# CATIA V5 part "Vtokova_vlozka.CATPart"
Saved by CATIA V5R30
Part number: Vtokova_vlozka
Definition: EH 6400_12_30x43_0
Nomenclature: EH 6400_12_30x43_0
Source: Unknown
Description: PART--DESC
Bounding box of the stored display mesh (mm): x -19.55 to 19.55, y -19.55 to 19.55, z 77.7 to 132.7
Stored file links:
  E:\Bakalarka\Model\Forma_v7\Vtokova_vlozka.CATPart
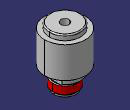
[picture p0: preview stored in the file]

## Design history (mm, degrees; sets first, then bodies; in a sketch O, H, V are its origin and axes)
Body1 "MANIFOLD_SOLID_BREP #3586" (main body)
  Solid1: solid without history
